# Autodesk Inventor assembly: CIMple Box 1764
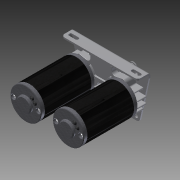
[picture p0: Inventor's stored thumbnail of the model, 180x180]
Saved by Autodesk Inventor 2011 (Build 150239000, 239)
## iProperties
Created: 2011-01
Part Number: CIMple Box 1764
Document SubType Name: Assembly
Designer: dfranz
Translation Standard: STEP AP203
FileName: S:/Products/Gearboxes Spur Single Stage/Single Stage Toughbox/CIMple Box.stp
PreProcessor: Unknown
PostProcessor: Build: 239, Release: 2011 RTM - Date: Wed 02/17/2010
Sent Units: millimeter
Uncertainty: 0.001
Author: dfranz
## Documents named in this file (16)
- R:\CAD Archives\Motors\CIMple Box 1764\CIMple Box 1764.iam
- R:\CAD Archives\Motors\CIMple Box 1764\Single d03 1764.ipt
- R:\CAD Archives\Motors\CIMple Box 1764\Single d04 1764.ipt
- R:\CAD Archives\Motors\CIMple Box 1764\Single d02 1764.ipt
- R:\CAD Archives\Motors\CIMple Box 1764\Single d05 1764.ipt
- R:\CAD Archives\Motors\CIMple Box 1764\CIMple Box Sticker 1764.ipt
- R:\CAD Archives\Motors\CIMple Box 1764\Single d01 1764.ipt
- R:\CAD Archives\Motors\CIMple Box 1764\10-32x0625 SHCS 1764.ipt
- R:\CAD Archives\Motors\CIMple Box 1764\250 Washer 1764.ipt
- R:\CAD Archives\Motors\CIMple Box 1764\14-20x0500 BHCS 1764.ipt
- R:\CAD Archives\Motors\CIMple Box 1764\10-32 Nylock Nut 1764.ipt
- R:\CAD Archives\Motors\CIMple Box 1764\125x124x700 Key 1764.ipt
- R:\CAD Archives\Motors\CIMple Box 1764\8mm Spring Clip 1764.ipt
- R:\CAD Archives\Motors\CIMple Box 1764\R6ZZ 1764.ipt
- R:\CAD Archives\Motors\CIMple Box 1764\FR-8-ZZ 1764.ipt
- R:\CAD Archives\Motors\CIMple Box 1764\CIM Motor 1764\CIM Motor 1764.ipt
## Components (28 placed, 15 different names)
1. Single d01 1764:1 — Mate:1, Mate:3, Mate:5, Mate:7
2. 10-32x0625 SHCS 1764:1 — Mate:6
3. 10-32x0625 SHCS 1764:2
4. 10-32x0625 SHCS 1764:3
5. 10-32x0625 SHCS 1764:4
6. 10-32x0625 SHCS 1764:5
7. 10-32x0625 SHCS 1764:6
8. 10-32x0625 SHCS 1764:7
9. 10-32x0625 SHCS 1764:8 — Mate:4
10. R6ZZ 1764:1
11. Single d03 1764:1
12. Single d04 1764:1
13. Single d02 1764:1
14. FR-8-ZZ 1764:1
15. 8mm Spring Clip 1764:1
16. 8mm Spring Clip 1764:2
17. 250 Washer 1764:1
18. 14-20x0500 BHCS 1764:1
19. Single d05 1764:1
20. Single d05 1764:2
21. CIMple Box Sticker 1764:1
22. 10-32 Nylock Nut 1764:1
23. 10-32 Nylock Nut 1764:2
24. 10-32 Nylock Nut 1764:3
25. 10-32 Nylock Nut 1764:4
26. 125x124x700 Key 1764:1
27. CIM Motor 1764:1 — Mate:1, Mate:6, Mate:7
28. CIM Motor 1764:2 — Mate:3, Mate:4, Mate:5
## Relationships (6: Mate 6)
- Mate:1: Single d01 1764:1 ↔ CIM Motor 1764:1
- Mate:3: Single d01 1764:1 ↔ CIM Motor 1764:2
- Mate:4: 10-32x0625 SHCS 1764:8 ↔ CIM Motor 1764:2
- Mate:5: Single d01 1764:1 ↔ CIM Motor 1764:2
- Mate:6: 10-32x0625 SHCS 1764:1 ↔ CIM Motor 1764:1
- Mate:7: Single d01 1764:1 ↔ CIM Motor 1764:1
